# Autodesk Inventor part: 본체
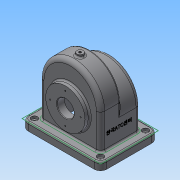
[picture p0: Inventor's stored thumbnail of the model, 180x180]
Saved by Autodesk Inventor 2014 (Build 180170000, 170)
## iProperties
Created: 2017-11
Part Number: 본체
Material: 일반
Document SubType Name: Modeling
Designer: NET
Density: 1 g/cm^3
Appearance: 기본값
Author: NET
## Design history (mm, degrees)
sketch "스케치2"
  geometry: L1 (58, 0)-(-58, 0); L2 (58, 0)-(58, 15); L3 (58, 15)-(58, 15); L4 (58, 15)-(58, 81); L5 (-58, 81)-(-58, 15); L6 (-58, 15)-(-58, 15); L7 (-58, 15)-(-58, 0); A1 r 58 centre (0, 81) between (58, 81) and (-58, 81); 2 further points
  constraints: 14 end point, 2 collinear, 2 equal length, 2 parallel, 2 perpendicular, 2 point on circle, 2 tangent, 1 centre point, 1 coincident, 1 horizontal, 1 midpoint, 1 vertical alignment
  dimensions: "d10" = 116 distance of L1.start L1.end; "d11" = 15 distance of L1.start L2.end; "d12" = 58 radius of A1; "d13" = 139 dimension on A1 L1
extrude "돌출1" new body sketch "스케치2" distance "d14" = 38; taper "d15" = 0 deg
sketch "스케치7"
  geometry: L1 (58, 0)-(-58, 0) reference; L2 (58, -57)-(-58, -57); L3 (58, 0)-(-58, 0); L4 (58, 0)-(58, -81) reference; L5 (58, -57)-(58, 0); L6 (58, 0)-(-58, 0); L7 (-58, -81)-(-58, 0) reference; L8 (-58, 0)-(-58, -57); A1 r 58 centre (0, -57) between (-58, -57) and (58, -57); 3 further points
  constraints: 10 end point, 2 midpoint, 2 point on circle, 2 tangent, 1 centre point, 1 parallel, 1 perpendicular, 1 vertical alignment
  dimensions: "d25" = 57 distance between parallel lines of L1 L2; "d26" = 58 radius of A1
extrude "돌출4" join sketch "스케치7" distance "d27" = 38; taper "d28" = 0 deg
sketch "스케치8"
  geometry: 1 further point
feature "쉘1" dims "d29" = 5
fillet "모깎기7" dims "d54" = 3, "d55" = 8
fillet "모깎기2" dims "d31" = 3
sketch "스케치9"
  geometry: L1 (-3, 8)-(-3, 68) reference; L2 (105, 0)-(5, 0) reference; L3 (113, 68)-(113, 8) reference; L4 (5, 76)-(105, 76) reference; L5 (5, 71)-(105, 71) reference; L6 (-20, 93)-(130, 93); L7 (130, 93)-(130, -17); L8 (130, -17)-(-20, -17); L9 (-20, -17)-(-20, 93); L10 (-3, 8)-(-3, 68) reference; L11 (105, 0)-(5, 0) reference; L12 (113, 68)-(113, 8) reference; L13 (5, 76)-(105, 76) reference; L14 (5, 71)-(105, 71) reference; L15 (108, 68)-(108, 8) reference; L16 (105, 5)-(5, 5) reference; L17 (2, 8)-(2, 68) reference; A1 r 3 centre (0, 73) between (0, 76) and (-3, 73) reference; A2 r 3 centre (0, 3) between (-3, 3) and (0, 0) reference; A3 r 3 centre (110, 3) between (110, 0) and (113, 3) reference; A4 r 3 centre (110, 73) between (113, 73) and (110, 76) reference; A5 r 3 centre (105, 68) between (108, 68) and (105, 71) reference; A6 r 3 centre (105, 8) between (105, 5) and (108, 8) reference; A7 r 3 centre (5, 8) between (2, 8) and (5, 5) reference; A8 r 3 centre (5, 68) between (5, 71) and (2, 68) reference; A9 r 8 centre (105, 68) between (113, 68) and (105, 76) reference; A10 r 8 centre (5, 68) between (5, 76) and (-3, 68) reference; A11 r 8 centre (5, 8) between (-3, 8) and (5, 0) reference; A12 r 8 centre (105, 8) between (105, 0) and (113, 8) reference; 5 further points
  constraints: 8 end point, 4 midpoint, 2 parallel, 1 horizontal, 1 horizontal alignment, 1 perpendicular, 1 vertical alignment
  dimensions: "d32" = 150 distance of L6.start L6.end; "d33" = 110 distance of L6.end L7.end
extrude "돌출5" join sketch "스케치9" distance "d34" = 15; taper "d35" = 0 deg
sketch "스케치12"
  geometry: L1 (0, 0)-(100, 0) reference; L2 (-8, -68)-(-8, -8) reference; L3 (100, -76)-(0, -76) reference; L4 (108, -8)-(108, -68) reference; L5 (-25, 17)-(125, 17); L6 (125, 17)-(125, -93); L7 (125, -93)-(-25, -93); L8 (-25, -93)-(-25, 17); L9 (0, 0)-(100, 0) reference; L10 (-8, -68)-(-8, -8) reference; L11 (100, -76)-(0, -76) reference; L12 (108, -8)-(108, -68) reference; L13 (0, -5)-(100, -5) reference; L14 (103, -8)-(103, -68) reference; L15 (100, -71)-(0, -71) reference; L16 (-3, -68)-(-3, -8) reference; A1 r 8 centre (100, -8) between (108, -8) and (100, 0) reference; A2 r 8 centre (0, -8) between (0, 0) and (-8, -8) reference; A3 r 8 centre (0, -68) between (-8, -68) and (0, -76) reference; A4 r 8 centre (100, -68) between (100, -76) and (108, -68) reference; A5 r 8 centre (100, -8) between (108, -8) and (100, 0) reference; A6 r 8 centre (0, -8) between (0, 0) and (-8, -8) reference; A7 r 8 centre (0, -68) between (-8, -68) and (0, -76) reference; A8 r 8 centre (100, -68) between (100, -76) and (108, -68) reference; A9 r 3 centre (100, -8) between (103, -8) and (100, -5) reference; A10 r 3 centre (100, -68) between (100, -71) and (103, -68) reference; A11 r 3 centre (0, -68) between (-3, -68) and (0, -71) reference; A12 r 3 centre (0, -8) between (0, -5) and (-3, -8) reference; 5 further points
  constraints: 8 end point, 4 midpoint, 2 parallel, 1 horizontal, 1 horizontal alignment, 1 perpendicular, 1 vertical alignment
  dimensions: "d56" = 150 distance of L5.start L5.end; "d57" = 110 distance of L5.end L6.end
extrude "돌출7" join sketch "스케치12" distance "d58" = 15; taper "d59" = 0 deg
sketch "스케치13"
  geometry: L1 (-75, 0)-(75, 0) reference; C1 r 37.5 at (0, 65); 2 further points
  constraints: 1 centre point, 1 midpoint, 1 vertical alignment
  dimensions: "d60" = 65 distance from line of L1 C1.centre; "d61" = 75 diameter of C1
extrude "돌출8" join sketch "스케치13" distance "d62" = 9; taper "d63" = 0 deg
hole "구멍2" diameter "d66" = 32; stored, may be unused: countersink angle "d70" = 90 deg, drill point angle "d72" = 118 deg; dims "d64" = 10, "d65" = 10, "d67" = 6, "d68" = 4, "d69" = 2, "d71" = 8
fillet "모깎기8" dims "d73" = 3
sketch "스케치14"
  geometry: L1 (25, 17)-(-125, 17) reference; L2 (-125, 17)-(-125, -93) reference; L3 (-125, -93)-(25, -93) reference; L4 (25, -93)-(25, 17) reference; L5 (11, -68)-(11, -8) reference; L6 (-100, -79)-(0, -79) reference; L7 (-111, -8)-(-111, -68) reference; L8 (0, 3)-(-100, 3) reference; A1 r 11 centre (0, -8) between (11, -8) and (0, 3) reference; A2 r 11 centre (0, -68) between (0, -79) and (11, -68) reference; A3 r 11 centre (-100, -68) between (-111, -68) and (-100, -79) reference; A4 r 11 centre (-100, -8) between (-100, 3) and (-111, -8) reference; 1 further point
fillet "모깎기9" dims "d74" = 12
sketch "스케치15"
  geometry: A1 r 12 centre (-113, -81) between (-125, -81) and (-113, -93) reference; 2 further points
  constraints: 1 coincident
hole "구멍3" sketch "스케치15" at (-113, -81) diameter "d75" = 5; stored, may be unused: countersink angle "d79" = 90 deg, drill point angle "d81" = 118 deg; dims "d76" = 6, "d77" = 12, "d78" = 5, "d80" = 8
fillet "모깎기10" dims "d82" = 3
chamfer "모따기1" distance "d83" = 1; stored, may be unused: second distance "d84" = 2, angle "d85" = 45 deg
sketch "스케치16"
  geometry: 1 further point
sketch "스케치17"
  geometry: C1 r 37.5 at (0, 0) reference; 2 further points
  constraints: 1 vertical alignment
  dimensions: "d86" = 29 distance of C1.centre point (0, 29)
hole "구멍4" sketch "스케치17" at (0, 29) diameter "d87" = 2.459; stored, may be unused: countersink angle "d91" = 82 deg, drill point angle "d93" = 118 deg; dims "d88" = 6, "d89" = 3.023, "d90" = 5, "d92" = 8
sketch "스케치18"
  geometry: 1 further point
node "작업 평면3"
sketch "스케치19"
  geometry: L1 (50, -38)-(-50, -38) reference; C1 r 6 at (0, -19); 1 further point
  constraints: 1 centre point, 1 vertical alignment
  dimensions: "d98" = 19 distance from line of L1 C1.centre; "d99" = 12 diameter of C1
extrude "돌출9" join sketch "스케치19" stored distance "d100" = 9; taper "d101" = 0 deg
hole "구멍5" diameter "d104" = 4.459; stored, may be unused: countersink angle "d108" = 82 deg, drill point angle "d110" = 0 deg; dims "d105" = 24, "d106" = 3.023, "d107" = 5, "d109" = 8, "d112" = 10, "d113" = 10
fillet "모깎기11" dims "d111" = 3
sketch "스케치20"
  geometry: 1 further point
sketch "스케치21"
  geometry: C1 r 16 at (0, -65) reference; C2 r 31 at (0, -65); 1 further point
  constraints: 1 centre point, 1 coincident
  dimensions: "d114" = 62 diameter of C2
extrude "돌출10" join sketch "스케치21" distance "d115" = 9; taper "d116" = 0 deg
fillet "모깎기12" dims "d117" = 3
chamfer "모따기2" distance "d118" = 1; stored, may be unused: second distance "d119" = 2, angle "d120" = 45 deg
sketch "스케치22"
  geometry: C1 r 31 at (0, 0) reference; 2 further points
  constraints: 1 vertical alignment
  dimensions: "d121" = 26 distance of C1.centre point (0, -26)
hole "구멍6" sketch "스케치22" at (0, -26) diameter "d122" = 2.459; stored, may be unused: countersink angle "d126" = 90 deg, drill point angle "d128" = 118 deg; dims "d123" = 6, "d124" = 4, "d125" = 2, "d127" = 8
sketch "스케치23"
  geometry: L1 (8.001, -3.455)-(8.001, 4.256); L2 (8.001, 4.256)-(21.334, 4.256); L3 (21.334, 4.256)-(21.334, -3.455); L4 (21.334, -3.455)-(8.001, -3.455); L5 (39, 33)-(39, -27) reference; L6 (0, 33)-(39, 33) reference; L7 (0, 0)-(0, 33) reference; L8 (-24, 0)-(0, 0) reference; L9 (-24, 0)-(-24, -27) reference; L10 (39, -27)-(-24, -27) reference; 1 further point
  constraints: 2 other
feature "엠보싱1" sketch "스케치23" dims "d10" = 116, "d11" = 15, "d12" = 58, "d13" = 139, "d132" = 0.5, "d133" = 0
node "솔리드1"
mirror "대칭3"
mirror "대칭4"
pattern_circular "원형 패턴1" dims angle "d95" = 360 deg
mirror "대칭5"
pattern_circular "원형 패턴2" dims angle "d130" = 360 deg
node "투영된 루프4"
node "투영된 루프5"
node "투영된 루프6"
other parameters: "d97" = 144
